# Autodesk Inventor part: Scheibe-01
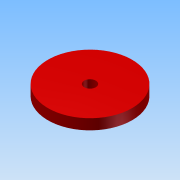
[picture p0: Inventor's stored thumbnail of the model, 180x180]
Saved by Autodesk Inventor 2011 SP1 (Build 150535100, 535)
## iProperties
Created: 2010-12
Part Number: Scheibe-01
Material: Standard
Document SubType Name: Modeling
Designer: Udo.Huebner
Density: 1 g/cm^3
Author: Udo.Huebner
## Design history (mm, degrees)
derived "002-Scheiben.ipt" dims "d1" = 11, "d3" = 0, "d4" = 0, "d5" = 0
node "Volumenkörper1"
feature "Volumenkörper1::002-Scheiben.ipt" dims "d1" = 11, "d2" = 10, "d3" = 0, "d4" = 0, "d5" = 0, "AD" = 80, "ScaleForDerivedMember" = 10
tag "Bezeichnung1"
